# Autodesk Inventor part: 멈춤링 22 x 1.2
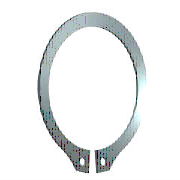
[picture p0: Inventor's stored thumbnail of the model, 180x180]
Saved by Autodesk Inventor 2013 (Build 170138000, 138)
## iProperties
IsCustomPart: 0
Company: 한국ATC센터
Created: 2014-07
Part Number: 멈춤링 22 x 1.2
Material: Steel, Mild
Description: 리테이닝 링(C형)
Document SubType Name: Modeling
Standard: KS B 1336
Designer: KYOUNG IL JANG
Standards Organization: KS
Language: ko-KR
Size Designation: 22 x 1.2
Categories: <MemberInstance><Categories><Category DisplayName="샤프트 부품" InternalName="7f7aeb1f-a693-4053-b835-cee3144e0d98" Mnemonic="SHFT"><Category DisplayName="써클립" Inter
Density: 7.86 g/cm^3
Mass: 1.8286 g
Surface Area: 5.91219 cm^2
Volume: 0.232646 cm^3
Author: KYOUNG IL JANG
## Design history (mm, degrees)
sketch "스케치1"
  geometry: L1 (-6, 0)-(6, 0) reference; L2 (0, 20.189)-(0, -80.536) reference; L3 (-48.09, 0)-(48.09, 0) reference; L4 (-0.5, -21.488)-(-0.5, -25.588); L5 (-0.5, -6.54)-(-0.5, -13.29); L6 (-2.795, 2.7)-(3.672, 2.7); L7 (0.5, -6.54)-(0.5, -13.29); L8 (0.5, -21.488)-(0.5, -25.588); C1 r 1 at (-2, -23.437); C2 r 1 at (2, -23.437); A1 r 10.5 centre (0, -11) between (0.5, -21.488) and (-0.5, -21.488); A2 r 13.025 centre (0, -10.325) between (5.149, -22.289) and (-5.149, -22.289); A3 r 14.597 centre (0, -11) between (-2.318, -25.411) and (-0.5, -25.588); A4 r 2 centre (-2, -23.437) between (-3.97, -23.781) and (-2.318, -25.411); A5 r 2 centre (-5.94, -24.126) between (-3.97, -23.781) and (-5.149, -22.289); A6 r 2 centre (5.94, -24.126) between (5.149, -22.289) and (3.97, -23.781); A7 r 2 centre (2, -23.437) between (2.318, -25.411) and (3.97, -23.781); A8 r 14.597 centre (0, -11) between (0.5, -25.588) and (2.318, -25.411)
  constraints: 16 point on circle, 12 end point, 10 centre point, 9 symmetric about line, 5 point on line, 4 tangent, 3 coincident, 2 horizontal, 1 perpendicular, 1 vertical, 5 other
  dimensions: "d0" = 21 diameter of A1 (= ND); "d1" = 4.1 distance of L4.end L4.start (= SRB2); "d6" = 0.5 distance between parallel lines of L2 L5 (= 0.25 x SD5); "d7" = 2.7 distance between parallel lines of L6 L3 (= SRB1); "d8" = 0.675 distance of A1.centre A2.centre (= 0.25 x SRB1); "d9" = 2 radius of A4 (= SD5); "d10" = 2 radius of A5 (= SD5); "d11" = 1.5 distance from line of L4 A4.centre (= 0.75 x SD5); "d12" = 2 diameter of C1 (= SD5); "d13" = 2 diameter of C2 (= SD5); "d14" = 11 distance from line of A1.centre L1 (= 0.5 x WD)
extrude "본체" new body sketch "스케치1" distance "d2" = 1.2 (= SD); taper "d3" = 0 deg
workaxis "Work Axis1"
workplane "Work Plane1"
body "Solid1"
other parameters: "WD" = 22 (= WDMIN) [user parameter; used in 1 equation term], "SD" = 1.2 [user parameter; used in 1 equation term], "SRB1" = 2.7 [user parameter; used in 2 equation terms], "ND" = 21 [user parameter; used in 1 equation term], "SRB2" = 4.1 [user parameter; used in 1 equation term], "SD5" = 2 [user parameter; used in 6 equation terms], "d15" = 0, "d16" = 0, "d17" = 0, "d41" = 0, "d42" = 0, "WDMIN" = 22 [user parameter; used in 1 equation term], "SD3" = 20.5 [user parameter], "WDMAX" = 24 [user parameter]
